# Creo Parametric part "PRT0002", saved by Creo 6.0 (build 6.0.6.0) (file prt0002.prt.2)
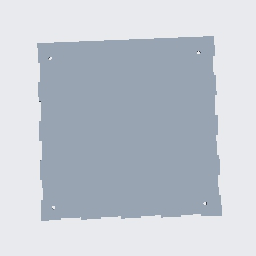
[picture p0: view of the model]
Units: Inch lbm Second (Pro/E Default); INCH, POUND, SECS

Created from: INLBS_PART_SOLID.PRT

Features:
  1. datum plane "RIGHT"
  2. datum plane "TOP"
  3. datum plane "FRONT"
  4. coordinate system
  5. sketch "Sketch 1"
  6. extrusion "Extrude 1"
  7. sketch "Sketch 2"
  8. extruded cut "Extrude 2"

Surfaces: 54 plane, 4 cylinder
